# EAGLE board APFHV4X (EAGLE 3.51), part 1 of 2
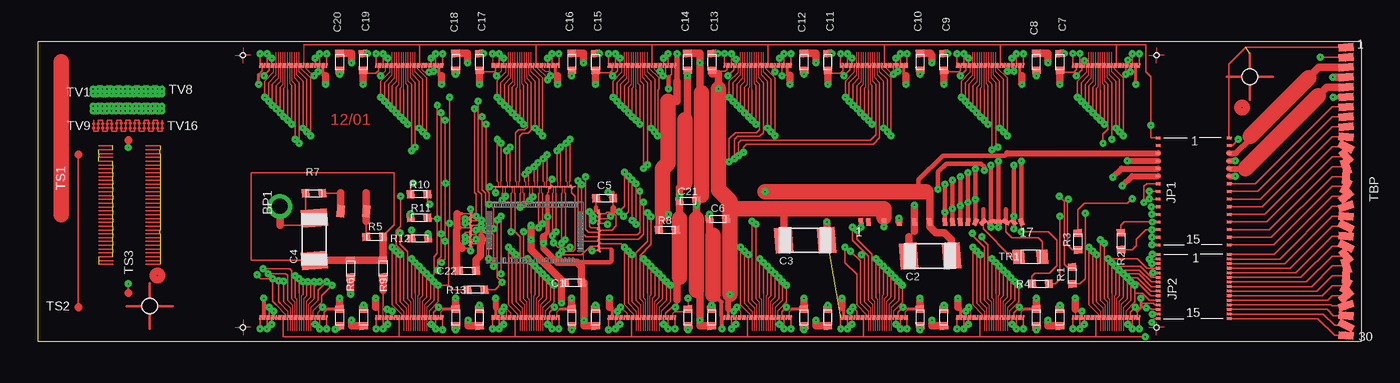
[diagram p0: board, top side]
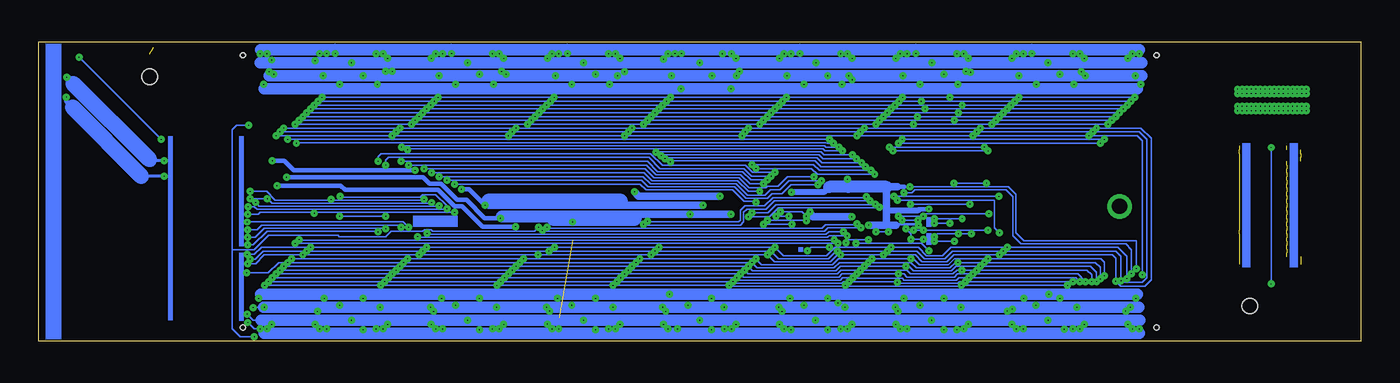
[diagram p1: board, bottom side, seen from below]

Size 86.6 x 19.6 mm. Coordinates in mm from the lower left corner, seen from the top.
Outline: 0,0 86.6,0 86.6,19.6 0,19.6 0,0
Copper layers used: Top, Bottom
Holes 0.3 mm at 73.2,18.7 73.2,0.9 13.4,0.9 13.4,18.7
Holes 1 mm at 79.3,17.3 7.3,2.3
tRestrict: area 77.3,-9.6 to 87.3,3.4

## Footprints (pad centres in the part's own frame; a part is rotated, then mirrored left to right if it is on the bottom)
200 = smd 0.5 x 0.3 rotated 5.8:  0,0
02 = smd 0.5 x 0.55 rotated 4.3:  -0.55,0 | smd 0.5 x 0.55 rotated 4.4:  0.55,0
06 = smd 1.15 x 1.7 rotated 4.3:  -1.4,0 | smd 1.15 x 1.7 rotated 4.4:  1.4,0
GTAIL = smd 0.3 x 0.5 rotated 4.3:  0,0;  7,0 | smd 0.3 x 0.5 rotated 4.4:  0.5,0 | smd 0.3 x 0.5 rotated 4.5:  1.5,0 | smd 0.3 x 0.5 rotated 4.6:  2.5,0 | smd 0.3 x 0.5 rotated 4.7:  3.5,0;  4.5,0 | smd 0.3 x 0.5 rotated 4.8:  5.5,0 | smd 0.3 x 0.5 rotated 4.9:  6,0 | smd 0.3 x 0.5 rotated 5:  6.5,0 | smd 0.3 x 0.5 rotated 26.8:  7.5,0 | smd 0.3 x 0.5 rotated 49.3:  8,0 | smd 0.3 x 0.5 rotated 71.8:  8.5,0 | smd 0.3 x 0.5 rotated 94.3:  9,0 | smd 0.3 x 0.5 rotated 116.8:  9.5,0 | smd 0.3 x 0.5 rotated 139.3:  10,0 | smd 0.3 x 0.5 rotated 161.8:  10.5,0
BP30 = smd 1 x 0.5 rotated 4.3:  0,9.425;  0,3.575 | smd 1 x 0.5 rotated 4.4:  0,8.775;  0,-2.925 | smd 1 x 0.5 rotated 4.5:  0,8.125;  0,-9.425 | smd 1 x 0.5 rotated 4.6:  0,7.475 | smd 1 x 0.5 rotated 4.7:  0,6.825;  0,6.175 | smd 1 x 0.5 rotated 4.8:  0,5.525 | smd 1 x 0.5 rotated 4.9:  0,4.875 | smd 1 x 0.5 rotated 5:  0,4.225 | smd 1 x 0.5 rotated 26.8:  0,2.925 | smd 1 x 0.5 rotated 49.3:  0,2.275 | smd 1 x 0.5 rotated 71.8:  0,1.625 | smd 1 x 0.5 rotated 94.3:  0,0.975 | smd 1 x 0.5 rotated 116.8:  0,0.325 | smd 1 x 0.5 rotated 139.3:  0,-0.325 | smd 1 x 0.5 rotated 161.8:  0,-0.975 | smd 1 x 0.5 rotated 184.3:  0,-1.625 | smd 1 x 0.5 rotated 206.8:  0,-2.275 | smd 1 x 0.5 rotated 26.9:  0,-3.575 | smd 1 x 0.5 rotated 49.4:  0,-4.225 | smd 1 x 0.5 rotated 71.9:  0,-4.875 | smd 1 x 0.5 rotated 94.4:  0,-5.525 | smd 1 x 0.5 rotated 116.9:  0,-6.175 | smd 1 x 0.5 rotated 139.4:  0,-6.825 | smd 1 x 0.5 rotated 161.9:  0,-7.475 | smd 1 x 0.5 rotated 184.4:  0,-8.125 | smd 1 x 0.5 rotated 206.9:  0,-8.775
-I = smd 0.1 x 0.3 rotated 5.8: 0 1.525,0; 0 3.025,0; 0 4.525,0; 1 1.675,0; 1 3.175,0; 1 4.675,0; 2 1.825,0; 2 3.325,0; 2 4.825,0; 3 1.975,0; 3 3.475,0; 3 4.975,0; 4 2.125,0; 4 3.625,0; 4 5.125,0; 5 2.275,0; 5 3.775,0; 5 5.275,0; 6 2.425,0; 6 3.925,0; 6 5.425,0; 7 2.575,0; 7 4.075,0; 7 5.575,0; 8 2.725,0; 8 4.225,0; 8 5.725,0; 9 2.875,0; 9 4.375,0; 9 5.875,0
-SP = smd 0.5 x 0.8 rotated 5.8:  0,0
ACK15C = smd 0.3 x 0.2 rotated 5.8: 0 4.65,0.75; 0 4.65,-0.75; 0 4.65,-2.25; 1 0,0.45; 1 0,-1.05; 2 4.65,0.45; 2 4.65,-1.05; 3 0,0.15; 3 0,-1.35; 4 4.65,0.15; 4 4.65,-1.35; 5 0,-0.15; 5 0,-1.65; 6 4.65,-0.15; 6 4.65,-1.65; 7 0,-0.45; 7 0,-1.95; 8 4.65,-0.45; 8 4.65,-1.95; 9 0,-0.75; 9 0,-2.25;  0,1.95;  4.65,1.95;  0,1.65;  4.65,1.65;  0,1.35;  4.65,1.35;  0,1.05;  4.65,1.05;  0,0.75
ACK15 = smd 0.3 x 0.2 rotated 5.8: 0 4.65,1.5; 0 4.65,-1; 0 4.65,-3.5; 1 0,1; 1 0,-1.5; 2 4.65,1; 2 4.65,-1.5; 3 0,0.5; 3 0,-2; 4 4.65,0.5; 4 4.65,-2; 5 0,0; 5 0,-2.5; 6 4.65,0; 6 4.65,-2.5; 7 0,-0.5; 7 0,-3; 8 4.65,-0.5; 8 4.65,-3; 9 0,-1; 9 0,-3.5;  0,3.5;  4.65,3.5;  0,3;  4.65,3;  0,2.5;  4.65,2.5;  0,2;  4.65,2;  0,1.5
03 = smd 0.75 x 0.95 rotated 4.4:  0.775,0 | smd 0.75 x 0.95 rotated 4.3:  -0.775,0
C_DSM = smd 0.3 x 0.1 rotated 97.6: 0 6.9,-4.175; 1 6.9,-2.825; 2 6.9,-1.775; 4 -1.5,-1.925; 5 -1.5,-2.825; 6 -1.5,-4.175 | smd 0.3 x 0.1 rotated 321.2: 0 6.9,-4.325; 1 6.9,-2.975; 2 6.9,-1.925; 4 -1.5,-1.775; 5 -1.5,-2.675; 6 -1.5,-4.025 | smd 0.1 x 0.3 rotated 96: 0N 4.95,-0.15; 0P 4.8,-0.15; 1N 4.35,-0.15; 1P 4.2,-0.15; 2N 3.45,-0.15; 2P 3.3,-0.15; 3N 2.85,-0.15; 3P 2.7,-0.15; 4N 2.25,-0.15; 4P 2.1,-0.15; 5N 1.65,-0.15; 5P 1.5,-0.15; 6N 1.05,-0.15; 6P 0.9,-0.15; 7N 0.45,-0.15; 7P 0.3,-0.15; 8N 0.15,-0.15; 8P 0,-0.15; 9N 0.75,-0.15; 9P 0.6,-0.15; 10N 1.35,-0.15; 10P 1.2,-0.15; 11N 1.95,-0.15; 11P 1.8,-0.15; 12N 2.55,-0.15; 12P 2.4,-0.15; 13N 3.15,-0.15; 13P 3,-0.15; 14N 4.05,-0.15; 14P 3.9,-0.15; 15N 4.65,-0.15; 15P 4.5,-0.15 | smd 0.3 x 0.1 rotated 96: 2N 6.9,-3.575; 2P 6.9,-3.425; N 6.9,-3.275; P 6.9,-3.125 | smd 0.1 x 0.3 rotated 97.6: 3 3.6,-0.15 | smd 0.1 x 0.3 rotated 321.2: 3 3.75,-0.15 | smd 0.1 x 0.3 rotated 74.7: B 5.25,-0.15 | smd 0.3 x 0.1 rotated 74.7: B 6.9,-3.725 | smd 0.3 x 0.1 rotated 209.8: CN -1.5,-3.575; CP -1.5,-3.725 | smd 0.3 x 0.1 rotated 298.2: DSM -1.5,-3.875 | smd 0.3 x 0.1 rotated 75.2: INN -1.5,-3.275; INP -1.5,-3.425; N -1.5,-2.975; P -1.5,-3.125 | smd 0.3 x 0.1 rotated 141.7: N -1.5,-2.075; P -1.5,-2.225 | smd 0.3 x 0.1 rotated 73.5: N 6.9,-2.525; P 6.9,-2.375 | smd 0.3 x 0.1 rotated 97.3: ON -1.5,-2.375; OP -1.5,-2.525 | smd 0.3 x 0.1 rotated 74.9: OUT 6.9,-2.675 | smd 0.1 x 0.3 rotated 28.5:  5.1,-0.15 | smd 0.3 x 0.1 rotated 253.4:  6.9,-2.225;  6.9,-2.075 | smd 0.3 x 0.1 rotated 73.4:  6.9,-3.875 | smd 0.3 x 0.1 rotated 96.7:  6.9,-4.025

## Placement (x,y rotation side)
BP1  SENSOR  [200]  15.82,8.83 270 top
C1  0.1  [02]  35.02,3.83 0 top
C2  4.7  [06]  58.38,5.58 180 top
C3  4.7  [06]  50.2,6.6 180 top
C4  .001 1kV  [06]  18.07,6.68 270 top
C5  0.1  [02]  37.07,9.35 180 top
C6  0.1  [02]  44.47,8 0 top
C7  0.1  [02]  66.88,18.27 90 top
C8  0.1  [02]  65.32,18.27 270 top
C9  0.1  [02]  59.27,18.27 90 top
C10  0.1  [02]  57.72,18.27 270 top
C11  0.1  [02]  51.67,18.27 90 top
C12  0.1  [02]  50.12,18.27 270 top
C13  0.1  [02]  44.1,18.27 90 top
C14  0.1  [02]  42.5,18.27 270 top
C15  0.1  [02]  36.47,18.27 90 top
C16  0.1  [02]  34.92,18.27 270 top
C17  0.1  [02]  28.87,18.27 90 top
C18  0.1  [02]  27.32,18.27 270 top
C19  0.1  [02]  21.27,18.27 90 top
C20  0.1  [02]  19.72,18.27 270 top
C21  0.1  [02]  42.52,9.18 0 top
C22  0.1  [02]  28.1,4.6 180 top
C23  0.1  [02]  19.72,1.55 270 top
C24  0.1  [02]  21.3,1.55 90 top
C25  0.1  [02]  27.32,1.55 270 top
C26  0.1  [02]  28.87,1.55 90 top
C27  0.1  [02]  34.92,1.55 270 top
C28  0.1  [02]  36.47,1.55 90 top
C29  0.1  [02]  42.52,1.55 270 top
C30  0.1  [02]  44.07,1.55 90 top
C31  0.1  [02]  50.12,1.55 270 top
C32  0.1  [02]  51.67,1.55 90 top
C33  0.1  [02]  57.72,1.55 270 top
C34  0.1  [02]  59.27,1.55 90 top
C35  0.1  [02]  65.32,1.55 270 top
C36  0.1  [02]  66.88,1.55 90 top
CN_PT_  PIGTAIL  [GTAIL]  53.85,7.8 0 top
CN_T  T_BP30  [BP30]  85.6,9.8 0 top
FE-0  FE-I  [-I]  73.6,18.05 180 top
FE-1  FE-I  [-I]  66,18.05 180 top
FE-2  FE-I  [-I]  58.4,18.05 180 top
FE-3  FE-I  [-I]  50.8,18.05 180 top
FE-4  FE-I  [-I]  43.2,18.05 180 top
FE-5  FE-I  [-I]  35.6,18.05 180 top
FE-6  FE-I  [-I]  28,18.05 180 top
FE-7  FE-I  [-I]  20.4,18.05 180 top
FE-8  FE-I  [-I]  13,1.55 0 top
FE-9  FE-I  [-I]  20.6,1.55 0 top
FE-10  FE-I  [-I]  28.2,1.55 0 top
FE-11  FE-I  [-I]  35.8,1.55 0 top
FE-12  FE-I  [-I]  43.4,1.55 0 top
FE-13  FE-I  [-I]  51,1.55 0 top
FE-14  FE-I  [-I]  58.6,1.55 0 top
FE-15  FE-I  [-I]  66.2,1.55 0 top
HV_PT1  VDET  [-SP]  19.8,8.5 180 top
HV_PT2  VDET_ret  [-SP]  21.47,8.5 180 top
JP2_  JPACK15C  [ACK15C]  73.3,3.73 0 top
JPA_  JPACK15  [ACK15]  73.3,9.8 0 top
R1  Zout  [02]  67.67,4.3 270 top
R2  Zin  [02]  70.88,6.55 90 top
R3  Zout  [02]  68.05,6.53 90 top
R4  Zin  [02]  65.6,3.75 0 top
R5  1Ok  [02]  22.02,6.83 180 top
R6  *2  [02]  20.45,4.75 90 top
R7  10k  [02]  18.05,9.68 0 top
R8  0 *7  [02]  41.17,7.28 0 top
R9  *2  [02]  22.57,4.75 90 top
R10  110  [02]  24.92,9.62 180 top
R11  110  [02]  24.92,8.08 0 top
R12  110  [02]  24.97,6.73 0 top
R13  110  [02]  28.65,3.38 180 top
TR1  NTC 10k  [03]  64.95,5.53 180 top
U1  MCC_DSM  [C_DSM]  29.8,10.25 0 top

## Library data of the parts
BP1 C1-C36 CN_PT_ CN_T FE-0 FE-1-FE-15 HV_PT1 HV_PT2 JP2_ JPA_ R1-R13 TR1 U1 = 1X

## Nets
AGND: C3. C6. C7. C9. C11. C13. C15. C17. C19. C23. C25. C27. C29. C31. C33. C35. CN_PT_. FE-0.0 FE-0.3 FE-0.6 FE-0.9 FE-1.0 FE-1.3 FE-1.6 FE-1.9 FE-2.0 FE-2.3 FE-2.6 FE-2.9 FE-3.0 FE-3.3 FE-3.6 FE-3.9 FE-4.0 FE-4.3 FE-4.6 FE-4.9 FE-5.0 FE-5.3 FE-5.6 FE-5.9 FE-6.0 FE-6.3 FE-6.6 FE-6.9 FE-7.0 FE-7.3 FE-7.6 FE-7.9 FE-8.0 FE-8.3 FE-8.6 FE-8.9 FE-9.0 FE-9.3 FE-9.6 FE-9.9 FE-10.0 FE-10.3 FE-10.6 FE-10.9 FE-11.0 FE-11.3 FE-11.6 FE-11.9 FE-12.0 FE-12.3 FE-12.6 FE-12.9 FE-13.0 FE-13.3 FE-13.6 FE-13.9 FE-14.0 FE-14.3 FE-14.6 FE-14.9 FE-15.0 FE-15.3 FE-15.6 FE-15.9 JP2_.9 JPA_. R8. R9.
CCK: FE-0.1 FE-1.1 FE-2.1 FE-3.1 FE-4.1 FE-5.1 FE-6.1 FE-7.1 FE-8.1 FE-9.1 FE-10.1 FE-11.1 FE-12.1 FE-13.1 FE-14.1 FE-15.1 JP2_. U1.
CKN: CN_PT_. JPA_.7 R4. U1.
CKP: CN_PT_. JPA_.9 R4. U1.
DCIN: CN_PT_. JPA_.3 R2. U1.N
DCIP: CN_PT_. JPA_.5 R2. U1.P
DETV: BP1. C4. R7.
DGND: C1. C2. C5. C8. C10. C12. C14. C16. C18. C20. C21. C22. C24. C26. C28. C30. C32. C34. C36. CN_PT_. FE-0.4 FE-0.5 FE-0.6 FE-0.7 FE-0.8 FE-0.9 FE-1.4 FE-1.5 FE-1.7 FE-1.8 FE-1.9 FE-2.4 FE-2.5 FE-2.6 FE-2.8 FE-2.9 FE-3.4 FE-3.5 FE-3.8 FE-3.9 FE-4.4 FE-4.5 FE-4.6 FE-4.7 FE-4.9 FE-5.4 FE-5.5 FE-5.7 FE-5.9 FE-6.4 FE-6.5 FE-6.6 FE-6.9 FE-7.4 FE-7.5 FE-7.9 FE-8.4 FE-8.5 FE-8.6 FE-8.7 FE-8.8 FE-9.4 FE-9.5 FE-9.7 FE-9.8 FE-10.4 FE-10.5 FE-10.6 FE-10.8 FE-11.4 FE-11.5 FE-11.8 FE-12.4 FE-12.5 FE-12.6 FE-12.7 FE-13.4 FE-13.5 FE-13.7 FE-14.4 FE-14.5 FE-14.6 FE-15.4 FE-15.5 JP2_.5 JPA_. R8. U1.0 U1.1 U1.2 U1.3 U1.4 U1.5 U1.6 U1.DSM
DI: FE-0.2 FE-1.2 FE-2.2 FE-3.2 FE-4.2 FE-5.2 FE-6.2 FE-7.2 FE-8.2 FE-9.2 FE-10.2 FE-11.2 FE-12.2 FE-13.2 FE-14.2 FE-15.2 JP2_. U1.
DTO2N: CN_PT_. JPA_.1 R1. U1.2N
DTO2P: CN_PT_. JPA_.9 R1. U1.2P
DTON: CN_PT_. JPA_.7 R3. U1.N
DTOP: CN_PT_. JPA_.5 R3. U1.P
FE-0N: FE-0.4 U1.0N
FE-0P: FE-0.5 U1.0P
FE-1N: FE-1.4 U1.1N
FE-1P: FE-1.5 U1.1P
FE-2N: FE-2.4 U1.2N
FE-2P: FE-2.5 U1.2P
FE-3N: FE-3.4 U1.3N
FE-3P: FE-3.5 U1.3P
FE-4N: FE-4.4 U1.4N
FE-4P: FE-4.5 U1.4P
FE-5N: FE-5.4 U1.5N
FE-5P: FE-5.5 U1.5P
FE-6N: FE-6.4 U1.6N
FE-6P: FE-6.5 U1.6P
FE-7N: FE-7.4 U1.7N
FE-7P: FE-7.5 U1.7P
FE-8N: FE-8.4 U1.8N
FE-8P: FE-8.5 U1.8P
FE-9N: FE-9.4 U1.9N
FE-9P: FE-9.5 U1.9P
FE-10N: FE-10.4 U1.10N
FE-10P: FE-10.5 U1.10P
FE-11N: FE-11.4 U1.11N
FE-11P: FE-11.5 U1.11P
FE-12N: FE-12.4 U1.12N
FE-12P: FE-12.5 U1.12P
FE-13N: FE-13.4 U1.13N
FE-13P: FE-13.5 U1.13P
FE-14N: FE-14.4 U1.14N
FE-14P: FE-14.5 U1.14P
FE-15N: FE-15.4 U1.15N
FE-15P: FE-15.5 U1.15P
HV_GUARD: C4. R5. R6. R9.
LD: FE-0.3 FE-1.3 FE-2.3 FE-3.3 FE-4.3 FE-5.3 FE-6.3 FE-7.3 FE-8.3 FE-9.3 FE-10.3 FE-11.3 FE-12.3 FE-13.3 FE-14.3 FE-15.3 JP2_. U1.
LV1N: FE-0.0 FE-1.0 FE-2.0 FE-3.0 FE-4.0 FE-5.0 FE-6.0 FE-7.0 FE-8.0 FE-9.0 FE-10.0 FE-11.0 FE-12.0 FE-13.0 FE-14.0 FE-15.0 JP2_.5 R11. U1.N
LV1P: FE-0.1 FE-1.1 FE-2.1 FE-3.1 FE-4.1 FE-5.1 FE-6.1 FE-7.1 FE-8.1 FE-9.1 FE-10.1 FE-11.1 FE-12.1 FE-13.1 FE-14.1 FE-15.1 JP2_.7 R11. U1.P
N$1: CN_T. JPA_.
N$2: CN_T. JPA_.0
N$4: CN_T. JP2_.
N$5: CN_T. JP2_.
N$6: CN_T. JP2_.
N$7: CN_T. JPA_.0
N$8: CN_T. JP2_.
N$9: CN_T. JP2_.0
N$10: CN_T. JPA_.2
N$11: CN_T. JP2_.2
N$12: CN_T. JP2_.4
N$13: CN_T. JP2_.6
N$14: CN_T. JPA_.6
N$15: CN_T. JPA_.4
N$16: CN_T. JPA_.6
N$17: CN_T. JPA_.8
N$18: CN_T. JPA_.8
N$19: CN_T. JPA_.0
N$20: CN_T. JPA_.4
N$22: CN_T. JPA_.
N$23: CN_T. JPA_.
N$24: CN_T. JPA_.
N$25: CN_T. JPA_.2
N$26: CN_T. JP2_.8
N$27: CN_T. JP2_.0
N$28: CN_T. JP2_.2
N$29: CN_T. JP2_.6
N$30: CN_T. JP2_.8
N$32: CN_T. JP2_.4
N$33: CN_T. JP2_.0
NTC: CN_PT_. TR1.
NTC_RET: CN_PT_. TR1.
RSIB: CN_PT_. JPA_.3 U1.B
STRN: FE-0.2 FE-1.2 FE-2.2 FE-3.2 FE-4.2 FE-5.2 FE-6.2 FE-7.2 FE-8.2 FE-9.2 FE-10.2 FE-11.2 FE-12.2 FE-13.2 FE-14.2 FE-15.2 JP2_.9 R13. U1.ON
STRP: FE-0.3 FE-1.3 FE-2.3 FE-3.3 FE-4.3 FE-5.3 FE-6.3 FE-7.3 FE-8.3 FE-9.3 FE-10.3 FE-11.3 FE-12.3 FE-13.3 FE-14.3 FE-15.3 JP2_.1 R13. U1.OP
SYNCN: FE-0.6 FE-1.6 FE-2.6 FE-3.6 FE-4.6 FE-5.6 FE-6.6 FE-7.6 FE-8.6 FE-9.6 FE-10.6 FE-11.6 FE-12.6 FE-13.6 FE-14.6 FE-15.6 JP2_. R10. U1.CN
SYNCP: FE-0.7 FE-1.7 FE-2.7 FE-3.7 FE-4.7 FE-5.7 FE-6.7 FE-7.7 FE-8.7 FE-9.7 FE-10.7 FE-11.7 FE-12.7 FE-13.7 FE-14.7 FE-15.7 JP2_. R10. U1.CP
VCAL: CN_PT_. FE-0.0 FE-1.0 FE-2.0 FE-3.0 FE-4.0 FE-5.0 FE-6.0 FE-7.0 FE-8.0 FE-9.0 FE-10.0 FE-11.0 FE-12.0 FE-13.0 FE-14.0 FE-15.0 JPA_.
VDD: C1. C2. C5. C8. C10. C12. C14. C16. C18. C20. C21. C22. C24. C26. C28. C30. C32. C34. C36. CN_PT_. FE-0.4 FE-0.5 FE-1.4 FE-1.5 FE-2.4 FE-2.5 FE-3.4 FE-3.5 FE-4.4 FE-4.5 FE-5.4 FE-5.5 FE-6.4 FE-6.5 FE-7.4 FE-7.5 FE-8.4 FE-8.5 FE-9.4 FE-9.5 FE-10.4 FE-10.5 FE-11.4 FE-11.5 FE-12.4 FE-12.5 FE-13.4 FE-13.5 FE-14.4 FE-14.5 FE-15.4 FE-15.5 JP2_.7 JPA_. U1.0 U1.1 U1.2 U1.3 U1.4 U1.5 U1.6
VDDA: C3. C6. C7. C9. C11. C13. C15. C17. C19. C23. C25. C27. C29. C31. C33. C35. CN_PT_. FE-0.1 FE-0.2 FE-0.7 FE-0.8 FE-1.1 FE-1.2 FE-1.7 FE-1.8 FE-2.1 FE-2.2 FE-2.7 FE-2.8 FE-3.1 FE-3.2 FE-3.7 FE-3.8 FE-4.1 FE-4.2 FE-4.7 FE-4.8 FE-5.1 FE-5.2 FE-5.7 FE-5.8 FE-6.1 FE-6.2 FE-6.7 FE-6.8 FE-7.1 FE-7.2 FE-7.7 FE-7.8 FE-8.1 FE-8.2 FE-8.7 FE-8.8 FE-9.1 FE-9.2 FE-9.7 FE-9.8 FE-10.1 FE-10.2 FE-10.7 FE-10.8 FE-11.1 FE-11.2 FE-11.7 FE-11.8 FE-12.1 FE-12.2 FE-12.7 FE-12.8 FE-13.1 FE-13.2 FE-13.7 FE-13.8 FE-14.1 FE-14.2 FE-14.7 FE-14.8 FE-15.1 FE-15.2 FE-15.7 FE-15.8 JP2_.3 JPA_.1 R6.
VDET: HV_PT1. R7.
VDET_RET: HV_PT2. R5.
XCKN: FE-0.8 FE-1.8 FE-2.8 FE-3.8 FE-4.8 FE-5.8 FE-6.8 FE-7.8 FE-8.8 FE-9.8 FE-10.8 FE-11.8 FE-12.8 FE-13.8 FE-14.8 FE-15.8 JP2_.1 R12. U1.INN U1.N
XCKP: FE-0.9 FE-1.9 FE-2.9 FE-3.9 FE-4.9 FE-5.9 FE-6.9 FE-7.9 FE-8.9 FE-9.9 FE-10.9 FE-11.9 FE-12.9 FE-13.9 FE-14.9 FE-15.9 JP2_.3 R12. U1.INP U1.P

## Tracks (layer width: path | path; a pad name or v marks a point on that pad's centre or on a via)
AGND  (via drill 0.05 pad 0.2)  (1 unrouted)
  Top 0: v51.95,18.83 C11. | v67.15,18.83 C7. | v29.15,18.83 C17. | v67.15,18.83 C7. | 19.72,0.78 C23. | v27.32,0.75 C25. | v34.92,0.75 C27. | v57.72,0.75 C33. | v65.32,0.75 C35. | v67.15,18.83 C7. | 41.67,18.05 41.67,18.8 v41.82,18.8 | v50.12,0.75 C31. v50.12,0.75
  Top 0.075: v29.72,18.8 FE-5.9 | 22.57,1.55 22.57,2.3
  Top 0.1: v56.88,18.8 56.88,18.05 | v72.07,18.8 72.07,18.05 | v64.47,18.8 64.47,18.05 | FE-0.9 v67.72,18.83 67.72,18.43 | C7. 66.88,18.62 | 68.17,18.15 FE-0.6 v68.17,18.83 | v44.92,18.83 FE-3.9 | v60.12,18.8 FE-1.9 | v52.52,18.8 FE-2.9 | v37.32,18.8 FE-4.9 | 34.07,18.05 v34.07,18.8 | v26.47,18.8 26.47,18.05 | v22.12,18.8 FE-6.9 | v71.62,18.8 71.62,18.05 | v64.03,18.8 64.03,18.05 | v56.42,18.8 56.42,18.05 | v60.57,18.8 FE-1.6 | v52.97,18.8 FE-2.6 | v49.27,18.8 49.27,18.05 | v48.82,18.8 48.82,18.05 | v45.38,18.8 FE-3.6 | v41.22,18.8 41.22,18.05 | v37.77,18.8 FE-4.6 | v33.62,18.8 33.62,18.05 | v30.17,18.8 FE-5.6 | v18.87,18.8 18.87,18.05 | v18.42,18.8 18.42,18.05 | v14.52,18.8 FE-7.9 | v14.97,18.8 FE-7.6 | v14.52,0.8 14.52,1.55 | v14.97,0.8 14.97,1.55 | v18.87,0.8 FE-8.9 | v18.42,0.8 FE-8.6 | v22.12,0.8 22.12,1.55 | v22.57,0.8 22.57,1.55 | v26.47,0.75 FE-9.9 | v26.02,0.8 FE-9.6 | v29.72,0.8 29.72,1.55 | v30.17,0.8 30.17,1.55 | v34.07,0.8 FE-10.9 | v33.62,0.8 FE-10.6 | v37.32,0.75 37.32,1.55 | v37.77,0.8 37.77,1.55 | v45.38,0.8 45.38,1.55 | v41.67,0.8 FE-11.9 | v41.22,0.8 FE-11.6 | 44.75,1.55 44.92,1.55 | v49.27,0.8 FE-12.9 | v48.82,0.8 FE-12.6 | 52.52,1.55 v52.52,0.8 | v52.97,0.8 52.97,1.55 | v56.88,0.8 FE-13.9 | v56.42,0.8 FE-13.6 | v60.12,0.8 60.12,1.55 | v60.57,0.8 60.57,1.55 | v64.03,0.8 FE-14.6 | v64.47,0.8 FE-14.9 | v67.72,0.8 67.72,1.55 | v68.17,0.8 68.17,1.55 | v71.62,0.8 FE-15.6 | v72.07,0.8 FE-15.9 | JP2_.9 73.05,1.48 72.88,1.3 v72.88,1.23 | v26.02,18.8 26.02,18.05 | v22.57,18.8 FE-6.6 | 22.57,2.3 22.57,3.33 | 40.85,8.3 v41.25,8.3
  Top 0.2: v67.15,18.83 C7. | v59.55,18.83 C9. | v51.95,18.83 C11. | v36.75,18.83 C15. | v29.15,18.83 C17. | v21.55,18.83 C19. | v19.45,0.78 19.72,0.78 | v27.32,0.75 C25. | v34.92,0.75 C27. | v50.12,0.75 C31. | v57.72,0.75 C33. | v65.32,0.75 C35. | v44.5,18.83 C13. | v42.52,0.75 C29.
  Top 0.25: v44.75,0.8 44.75,1.55 44.75,1.6 44.72,1.62 44.72,2.55 44.22,3.05 44.17,3.05
  Top 0.35: 41.82,15.7 41.8,15.68 | v41.82,18.8 41.82,17
  Top 0.4: JPA_. 70.92,11.3 v70.35,10.73
  Top 0.5: 41.82,17 41.82,15.7 41.22,15.7 | v56.35,8.05 56.35,7.8 | 51.6,6.6 51.62,6.6 v51.62,7.8 | 44.17,7.03 43.92,7.03 43.92,8 v43.92,8.3 | 40.85,8.3 40.62,8.08 40.62,7.28 | 22.57,3.33 22.57,4.2
  Top 1: 40.85,8.3 40.85,11.28 41.22,11.65 41.22,15.7 | 44.17,3.05 44.17,6.93
  Bottom 0: 36.5,0.53 34.07,0.53 v34.07,0.8 33.77,0.78 | 36.5,0.53 36.5,0.65 | 36.5,0.53 37.32,0.53 v37.32,0.75 37.62,0.75 | 22.27,19.08 v22.12,18.8 v22.57,18.8 | 18.72,18.8 18.72,19.08 | 21.55,19.45 21.55,19.08 v21.55,18.83 21.2,19.18 20.85,19.18 20.47,18.8 v18.87,18.8 | 60.5,18.8 60.27,19.08 | 56.72,18.8 56.72,19.08 | 60.5,18.8 60.25,18.83 v59.55,18.83 | v59.55,18.83 59.52,18.8 | 64.32,18.8 64.32,19.08 | 64.32,18.8 64.42,18.8 64.45,18.83 C7. | v60.57,18.8 v64.03,18.8 | v60.57,18.8 60.5,18.8 | v64.03,18.8 64.32,18.8 | v59.55,18.83 59.55,19.45 | v59.55,18.83 59.55,19.08 | v59.55,18.83 v60.12,18.8 60.5,18.8 | v72.07,18.8 71.92,19.08 72.05,19.08 | v29.72,18.8 29.87,19.08 | 26.32,18.8 26.32,19.08 | v29.72,18.8 29.85,18.83 v29.15,18.83 | v29.15,18.83 29.12,18.8 v26.47,18.8 | v26.47,18.8 26.32,18.8 | v29.15,18.83 29.15,19.45 | v29.15,18.83 29.15,19.08 | v29.72,18.8 29.17,18.8 v29.15,18.83 | v29.15,18.83 26.35,18.83 26.32,18.8 | 26.32,18.8 26.1,18.8 | 26.1,18.8 v26.02,18.8 | v26.02,18.8 v22.57,18.8 | v67.15,18.83 67.15,19.45 | v67.15,18.83 67.15,19.08 | 56.85,18.83 v56.88,18.8 56.72,18.8 | v59.55,18.83 56.75,18.83 56.72,18.8 | 67.88,19.08 67.88,18.8 v67.72,18.83 | v67.72,18.83 v67.15,18.83 | v72.07,18.8 68.03,18.8 | v67.72,18.83 67.17,18.8 | v52.52,18.8 52.67,19.08 | v52.52,18.8 52.65,18.83 v51.95,18.83 | v51.95,18.83 51.92,18.8 | v52.97,18.8 v56.42,18.8 | v52.97,18.8 v52.52,18.8 | v56.42,18.8 56.72,18.8 | v51.95,18.83 51.95,19.45 | v51.95,18.83 51.95,19.08 | v52.52,18.8 51.97,18.8 v51.95,18.83 | v51.95,18.83 v49.27,18.8 49.27,19.08 | 41.52,18.8 41.52,19.08 | 41.3,18.8 41.65,18.83 | 41.52,18.8 41.55,18.83 | v37.32,18.8 37.47,19.08 36.75,19.08 v36.75,18.83
  Bottom 0: 33.92,19.08 33.92,18.8 | v37.32,18.8 37.45,18.83 v36.75,18.83 | v36.75,18.83 36.72,18.8 | 41.3,18.8 41.52,18.8 | v37.77,18.8 v41.22,18.8 | v41.22,18.8 41.3,18.8 | v37.32,18.8 v37.77,18.8 | v36.75,18.83 36.75,19.45 | v37.32,18.8 36.77,18.8 v36.75,18.83 | 33.7,18.8 33.92,18.8 | v33.62,18.8 33.7,18.8 | v33.62,18.8 v30.17,18.8 | v30.17,18.8 30.1,18.8 | 30.1,18.8 v29.72,18.8 | 34.05,18.83 34.02,18.8 33.92,18.8 | v36.75,18.83 33.95,18.83 33.92,18.8 | 14.67,19.08 14.67,18.8 v14.97,18.8 | 18.72,18.8 v18.42,18.8 | v18.42,18.8 v14.97,18.8 | v18.87,0.8 18.72,0.53 | v22.12,0.8 20.52,0.8 20.15,0.43 19.8,0.43 v19.45,0.78 19.35,0.78 19.32,0.8 v18.87,0.8 | v18.87,18.8 18.72,18.8 | 29.85,0.78 29.87,0.8 v30.17,0.8 | 29.77,0.75 29.82,0.75 | 29.77,0.75 v27.32,0.75 v26.47,0.75 26.32,0.8 | v33.62,0.8 v30.17,0.8 | v33.62,0.8 33.92,0.8 33.97,0.75 v34.92,0.75 34.97,0.8 37.47,0.8 | 37.47,0.8 37.45,0.78 | 37.47,0.8 37.55,0.8 | 41.67,0.53 v41.67,0.8 | 44.1,0.53 43.65,0.53 | v41.67,0.8 41.38,0.78 | 44.92,0.53 44.92,0.75 45.22,0.75 | 44.1,0.53 44.1,0.65 | 44.1,0.53 44.42,0.53 44.42,0.68 44.45,0.7 | v41.22,0.8 v37.77,0.8 | v41.67,0.8 v41.22,0.8 | v37.77,0.8 37.47,0.8 | 44.92,0.8 45.05,0.78 | 44.92,0.8 45.15,0.8 | 49.12,0.8 49.27,0.53 v49.27,0.8 | 51.7,0.53 50.12,0.53 v50.12,0.75 52.75,0.8 52.67,0.8 | 49.12,0.8 48.97,0.78 | 51.7,0.53 51.7,0.65 | 51.7,0.53 52.52,0.53 v52.52,0.8 52.82,0.75 | v48.82,0.8 v45.38,0.8 | 49.12,0.8 v48.82,0.8 | v45.38,0.8 44.92,0.8 | 52.67,0.8 52.65,0.78 | 56.88,0.53 56.72,0.8 | 56.88,0.53 59.3,0.53 | 56.72,0.8 56.57,0.78 | 60.12,0.53 60.12,0.75 60.42,0.75 | 59.3,0.53 59.3,0.65 | 59.3,0.53 60.12,0.53 | v52.97,0.8 v56.42,0.8 | v56.42,0.8 56.72,0.8 | v52.97,0.8 52.67,0.8
  Bottom 0: 60.27,0.8 60.25,0.78 | 60.27,0.8 60.35,0.8 | 56.72,0.8 v57.72,0.75 | 64.47,0.53 64.32,0.8 | 64.47,0.53 66.9,0.53 | 64.32,0.8 64.17,0.78 | 67.72,0.53 67.72,0.75 68.03,0.75 | 66.9,0.53 66.9,0.65 | 67.72,0.53 66.9,0.53 | v60.57,0.8 v64.03,0.8 | v64.03,0.8 64.32,0.8 | v60.57,0.8 60.27,0.8 | 67.88,0.8 67.85,0.78 | 67.88,0.8 67.95,0.8 v65.32,0.75 64.32,0.8 | v68.17,0.8 67.88,0.8 | v68.17,0.8 v71.62,0.8 | v71.62,0.8 71.92,0.8 | 14.67,0.53 v14.52,0.8 v14.97,0.8 | v14.97,0.8 v18.42,0.8 v18.87,0.8 | 42.52,0.53 v41.67,0.8 | 42.52,0.53 43.3,0.58 | 45.02,19.08 45.07,19.02 | 56.5,19.08 v56.42,18.8 | v72.07,18.8 v71.62,18.8 | 41.67,19.08 v41.82,18.8 41.67,19.05 41.7,19.08 | 44.5,19.08 v44.5,18.83 v44.92,18.83 45.3,18.83 45.3,19.08 | 48.9,19.08 48.9,18.8 | 41.3,19.08 41.3,18.8 | v67.72,18.83 v68.17,18.83 68.1,19.08 | 33.7,18.8 33.7,19.08 | 37.7,19.08 v37.77,18.8 | 30.1,18.8 30.1,19.08 | 26.47,19.08 v26.47,18.8 | 26.1,18.8 26.02,19.08 v26.02,18.8 | 22.5,19.08 v22.57,18.8 | 64.03,19.08 v64.03,18.8 | 64.47,19.08 v64.47,18.8 | 60.57,19.08 v60.57,18.8 | 52.97,19.08 v52.97,18.8 | 48.82,19.08 v48.82,18.8 | 45.38,19.08 v45.38,18.8 | 41.22,19.08 v41.22,18.8 | v33.62,18.8 v34.07,18.8 34.07,19.08 | v30.17,18.8 30.17,19.08 | 18.87,19.08 v18.87,18.8 | 18.42,19.08 v18.42,18.8 | 14.52,19.08 v14.52,18.8 | 14.97,19.08 v14.97,18.8 | 14.97,0.53 v14.97,0.8 | 18.87,0.53 v18.87,0.8 | 22.57,0.53 v22.57,0.8 | 26.02,0.53 v26.02,0.8 | 29.77,0.75 29.77,0.58 29.72,0.53 v29.72,0.8 | 30.17,0.53 v30.17,0.8 | 33.62,0.53 v33.62,0.8 | 37.77,0.53 v37.77,0.8 | 45.38,0.53 v45.38,0.8 | 41.22,0.53 v41.22,0.8 | 42.52,0.53 v42.52,0.75 | 44.92,0.8 v44.75,0.8 44.75,0.53 | 48.82,0.53 v48.82,0.8 | 52.97,0.53 v52.97,0.8
  Bottom 0: 56.88,0.53 v56.88,0.8 | v56.42,0.8 56.42,0.55 56.45,0.53 | 60.12,0.53 v60.12,0.8 | 60.57,0.53 v60.57,0.8 | 64.03,0.53 v64.03,0.8 | 64.47,0.53 v64.47,0.8 | 67.72,0.53 v67.72,0.8 | 68.17,0.53 v68.17,0.8 | v71.62,0.8 71.62,0.53 72.07,0.53 v72.07,0.8 | 51.62,8.05 v51.62,7.8
  Bottom 0.1: 71.92,0.8 v72.07,0.8 72.45,0.8 v72.88,1.23
  Bottom 0.3: v56.35,8.05 57.38,8.05 58.57,9.25 59.17,9.25 60.22,10.3 60.97,10.3 61.4,10.73 v70.35,10.73
  Bottom 0.5: 56.25,8.15 v56.35,8.05 | v41.25,8.3 v43.92,8.3 47.6,8.3 47.6,8.05
  Bottom 0.75: 64.47,0.53 66.62,0.53 | 33.62,0.53 34.07,0.53 37.32,0.53 37.77,0.53 | 22.57,0.53 18.87,0.53 14.97,0.53 14.52,0.53 | 14.52,19.08 14.97,19.08 18.42,19.08 18.87,19.08 21.55,19.08 22.27,19.08 22.5,19.08 26.02,19.08 26.47,19.08 30.1,19.08 30.17,19.08 33.7,19.08 33.92,19.08 34.07,19.08 37.47,19.08 37.7,19.08 41.22,19.08 41.3,19.08 41.67,19.08 41.7,19.08 44.5,19.08 45.02,19.08 45.3,19.08 45.38,19.08 48.82,19.08 48.9,19.08 49.27,19.08 52.97,19.08 56.5,19.08 60.57,19.08 64.03,19.08 64.47,19.08 68.1,19.08 72.05,19.08 | 42.52,0.53 41.67,0.53 41.22,0.53 | 71.8,0.53 71.62,0.53 68.17,0.53 67.72,0.53 64.47,0.53 | 22.57,0.53 26.02,0.53 29.72,0.53 30.17,0.53 33.62,0.53 | 22.57,0.53 22.12,0.53 | 52.52,0.53 50.12,0.53 | 37.77,0.53 33.62,0.53 | 42.52,0.53 43.65,0.53 44.42,0.53 44.75,0.53 44.92,0.53 45.38,0.53 48.82,0.53 49.27,0.53 50.12,0.53 | 42.52,0.53 41.22,0.53 | 41.22,0.53 37.77,0.53 | 50.12,0.53 52.97,0.53 56.45,0.53 56.88,0.53 60.12,0.53 60.57,0.53 64.03,0.53 64.47,0.53
  Bottom 0.8: 52.85,8.05 52.95,8.15 56.25,8.15
  Bottom 1: 47.6,8.05 51.62,8.05 52.85,8.05
CCK  (via drill 0.05 pad 0.2)
  Top 0.075: 17.82,17.23 17.22,17.83 17.22,18.05 | 25.42,17.23 24.82,17.83 24.82,18.05 | 33.02,17.23 32.42,17.83 32.42,18.05 | 40.62,17.23 40.02,17.83 40.02,18.05 | 48.22,17.23 47.62,17.83 47.62,18.05 | 55.82,17.23 55.22,17.83 55.22,18.05 | 63.42,17.23 62.82,17.83 62.82,18.05 | 71.03,17.23 70.42,17.83 70.42,18.05 | 15.57,2.38 16.17,1.78 16.17,1.55 | 23.17,2.38 23.77,1.78 23.77,1.55 | 30.77,2.38 31.37,1.78 31.37,1.55 | 38.38,2.38 38.97,1.78 38.97,1.55 | 53.57,2.38 54.17,1.78 54.17,1.55 | 61.17,2.38 61.77,1.78 61.77,1.55 | 68.78,2.38 69.38,1.78 69.38,1.55 | 45.97,2.38 46.57,1.78 46.57,1.55
  Top 0.1: v14.32,4.35 14.57,4.1 v15.35,4.1 15.35,2.6 15.57,2.38 | v72.92,5.68 73.3,5.68 | v17.82,13.45 17.82,17.23 | v25.42,13.45 25.42,17.23 | v33.02,13.45 33.02,17.23 | v40.52,13.45 40.57,13.45 40.57,16.45 40.62,16.5 40.62,17.23 | v48.22,13.45 48.22,17.23 | v55.82,13.45 55.82,17.23 | v63.42,13.45 63.42,17.23 | v71.03,13.45 71.03,17.23 | v23.17,6.15 23.17,2.38 | v30.77,6.15 30.77,2.38 | 38.38,2.38 v38.38,6.15 38.15,6.38 36.7,6.38 | 53.57,2.38 53.57,4.38 52.8,5.15 v52.8,6.15 | v61.17,6.15 61.17,2.38 | v68.78,6.15 68.78,2.38 | v45.97,6.15 45.97,2.38
  Bottom 0.1: v71.03,13.45 v63.42,13.45 v55.82,13.45 v48.22,13.45 v40.52,13.45 v33.02,13.45 v25.42,13.45 v17.82,13.45 14.65,13.45 14.32,13.12 v14.32,4.35 | v72.92,5.68 72.45,5.68 71.97,6.15 v68.78,6.15 v61.17,6.15 v52.8,6.15 v45.97,6.15 v38.38,6.15 37.82,5.6 35,5.6 34.45,6.15 v30.77,6.15 29,6.15 28.45,5.6 27.42,5.6 26.87,6.15 v23.17,6.15 15.92,6.15 15.35,5.58 v15.35,4.1
CKN  (via drill 0.05 pad 0.2)
  Top 0.1: v72.9,6.8 JPA_.7 | 63.85,7.8 v63.85,7.35 | v37.47,8.18 37.32,8.03 36.7,8.03 | v38.62,10.8 38.62,8.48 38.32,8.18 v38.3,8.18 | R4. 66.57,3.75 66.88,4.05 v66.88,8.18
  Top 0.3: v63.85,11.53 v63.85,8.18 63.85,7.8
  Bottom 0.1: v72.9,6.8 72.4,6.8 71.8,7.4 63.9,7.4 v63.85,7.35 | v38.62,10.8 39.9,10.8 40.4,11.3 45.9,11.3 46.62,12.03 63.67,12.03 63.85,11.85 v63.85,11.53 | v63.85,8.18 v66.88,8.18 | v38.3,8.18 v37.47,8.18
CKP  (via drill 0.05 pad 0.2)
  Top 0.1: v72.9,6.3 JPA_.9 | CN_PT_. v64.35,7.15 66.12,7.15 66.67,6.6 66.67,4.95 66.17,4.45 65.25,4.45 65.05,4.25 65.05,3.75 | v38.38,11.05 38.38,8.83 v38.02,8.48 | v36.32,8.18 U1.
  Top 0.3: v64.35,11.78 CN_PT_.
  Bottom 0.1: v72.9,6.3 72.53,6.3 71.62,7.2 64.4,7.2 v64.35,7.15 | v38.38,11.05 39.85,11.05 40.3,11.5 45.75,11.5 46.52,12.28 64.15,12.28 64.35,12.08 v64.35,11.78 | v36.32,8.18 36.62,8.48 v38.02,8.48
DCIN  (via drill 0.05 pad 0.2)
  Top 0.1: v72.92,7.8 JPA_.3 | 62.35,7.8 v62.35,7.45 | v72.92,7.8 72.9,7.83 | v39.12,7.65 v39.12,10.3 | 36.7,7.73 37.2,7.73 v37.27,7.65 | R2. 70.88,7.58 71.1,7.8 v72.92,7.8
  Top 0.3: v62.35,11.53 62.35,7.8
  Bottom 0.1: v62.35,7.45 62.7,7.8 v72.92,7.8 | v39.12,7.65 v37.27,7.65 | v39.12,10.3 40.02,10.3 40.62,10.9 46.17,10.9 46.8,11.53 v62.35,11.53
DCIP  (via drill 0.05 pad 0.2)  (1 unrouted)
  Top 0.1: v72.9,7.3 JPA_.5 | 62.85,7.8 v62.85,7.45 | v36.32,7.88 36.7,7.88 | v38.88,7.9 v38.88,10.55 | 70.88,6 71.62,6 71.88,6.25 71.88,6.68 72.5,7.3 72.88,7.3
  Top 0.3: v62.85,11.78 62.85,7.8
  Bottom 0.1: v72.9,7.3 72.28,7.3 71.97,7.6 63,7.6 v62.85,7.45 | v38.88,10.55 39.95,10.55 40.5,11.1 46.05,11.1 46.72,11.78 v62.85,11.78 | v36.32,7.88 36.32,7.9 v38.88,7.9
DETV  (via drill 1 pad 1.6)
  Top 0.1: 15.82,7.58 17.5,7.58 17.5,9.68 17.5,8.08 18.07,8.08
  Top 0.5: 15.82,7.58 BP1.
  other vias: 15.82,8.83
DGND  (via drill 0.05 pad 0.2)
  Top 0: 40.7,18.05 40.72,18.05 | 40.72,18.05 40.77,18.05 | 40.72,18.05 40.62,18.05 | 45.97,1.55 45.82,1.55 | 34.25,2.73 v34.25,2.5 34.2,3.8 34.45,3.8 34.47,3.83 | 37.62,8.58 37.62,8.43
  Top 0.005: 33.2,17.62 33.17,17.65
  Top 0.075: 61.02,1.53 61.02,1.55 61.02,2.13 v60.92,2.23 | 40.32,18.05 40.32,17.8 40.5,17.62 40.7,17.62 | v55.97,17.48 55.92,17.48 55.52,17.88 55.52,18.05 | v56.27,17.65 56.27,18.05 | 48.07,18.05 48.07,17.77 v48.22,17.62 | 32.72,18.05 32.72,17.83 33.32,17.23 v33.32,17.1 | 33.02,18.05 33.02,17.8 33.17,17.65 | FE-5.5 30.32,17.7 v30,17.38 | 25.12,18.05 25.12,17.77 25.3,17.6 v25.57,17.6 25.57,18.05 | FE-6.5 22.72,17.7 v22.4,17.38 | 33.47,17.62 33.2,17.62 | 33.47,17.62 33.55,17.62 v33.55,17.38 | 33.47,17.62 33.47,18.05 | 17.52,18.05 17.52,17.83 17.82,17.52 17.92,17.52 v18.07,17.38 | 18.27,18.05 18.27,17.68 v18.32,17.62 | FE-8.5 18.27,1.88 v18.62,2.23 | v23.17,1.98 23.17,1.55 | v30.5,2.23 30.55,2.23 30.62,2.15 | 30.62,2.15 30.62,1.55 | 30.92,1.55 30.92,1.85 30.62,2.15 | 38.52,1.55 38.52,1.83 v38.12,2.23 | v37.92,1.95 37.92,1.55 | 45.97,1.55 45.97,1.98 v45.72,2.23 | 53.12,1.55 v53.12,1.98 | v60.72,1.95 60.72,1.55 | U1.DSM U1.6 | 22.72,1.55 22.72,1.98 v22.85,2.1
  Top 0.1: 63.27,18.05 63.12,18.05 | 63.42,18.05 63.27,18.05 | 63.42,18.05 63.27,18.05 | v71.47,17.62 71.47,18.05 | v71.17,17.48 71.17,18.05 | 70.88,18.05 70.72,18.05 | 71.03,18.05 70.88,18.05 | 71.17,18.05 71.03,18.05 | 71.03,18.05 70.88,18.05 | 71.17,18.05 71.03,18.05 | v63.88,17.65 63.88,18.05 | v63.42,17.65 63.42,18.05 | FE-1.5 60.72,17.73 v60.38,17.38 | v55.97,17.48 55.97,18.05 | 55.52,18.05 55.67,18.05 | v48.67,17.38 48.67,18.05 | 48.07,18.05 47.92,18.05 | FE-4.5 37.92,17.7 v37.6,17.38 | v25.87,17.65 25.87,18.05 | FE-2.5 53.12,17.75 v52.75,17.38 | FE-0.5 68.32,17.75 v67.95,17.38 | FE-3.5 45.52,17.75 v45.15,17.38 | 41.07,18.05 41.07,17.55 v40.9,17.38 | FE-7.5 15.12,17.73 v14.77,17.38 | 15.72,1.55 15.57,1.55 15.42,1.55 v15.42,1.98 | v15.12,2.23 15.12,1.55 | 23.17,1.55 23.32,1.55 | FE-9.5 25.87,1.9 v26.2,2.23 | v30.32,1.98 30.32,1.55 | FE-10.5 33.47,1.9 v33.8,2.23 | v41.7,2.23 41.47,2.23 41.07,1.83 FE-11.5 | v45.52,1.95 45.52,1.55 | FE-12.5 48.67,1.93 v48.97,2.23 | 53.57,1.55 53.57,1.98 v53.32,2.23 | FE-13.5 56.27,1.9 v56.6,2.23 | FE-14.5 63.88,1.88 v64.22,2.23 | v68.32,1.95 68.32,1.55 | FE-15.5 71.47,1.9 v71.8,2.23 | JP2_.5 72.85,2.08 72.72,2.2 v72.53,2.2 | 41.82,2.6 41.82,2.73 | U1.2 37.12,8.33 37.22,8.43 37.62,8.43 37.82,8.23 37.82,7.55 37.55,7.28 U1.1 | U1.3 33.55,10.53 v33.62,10.6 | v36.25,5.93 U1.0 | U1.DSM 28.95,6.38 28.95,6.2 | 37.62,9.35 37.62,8.73 | 34.47,3.83 34.47,3.9 34.35,3.9 34.25,4 | v33.72,6.45 34.02,6.15 v34.82,6.15 | 28.3,8.58 U1.4 v28.3,8.65 | v28.97,7.58 U1.5 v28.97,7.58
  Top 0.15: 40.7,17.62 v40.7,17.65 40.7,17.7
  Top 0.2: 41.82,2.7 41.82,2.6 41.82,2.35 v41.7,2.23 | 40.7,17.7 40.7,18.05 | v21.3,2.35 C24. | v28.87,2.35 C26. | v36.47,2.35 C28. | v44.07,2.35 C30. | v51.67,2.35 C32. | v59.27,2.35 C34. | v66.88,2.35 C36. | v37.3,9.75 37.62,9.75 37.62,9.35
  Top 0.25: v28.97,7.58 28.97,6.93
  Top 0.3: 57.62,9.78 57.62,10.55 59.22,12.15 63.27,12.15 63.42,12.3 | v32.25,6.65 32.25,6.7
  Top 0.35: 28.97,6.93 29.05,6.85
  Top 0.4: 63.42,12.3 73.3,12.3 | 37.62,8.73 37.62,8.58 | 28.95,6.38 29.05,6.38 29.05,6.85
  Top 0.5: v65.32,17.38 C8. | v42.5,17.38 C14. 42.5,14.65 42.32,14.48 | v57.72,17.48 C10. | v50.12,17.48 C12. | v34.92,17.38 C16. | v27.32,17.48 C18. | v19.72,17.48 C20. | 42.32,10.38 41.97,10.03 v41.97,9.5 | 41.97,9.18 v41.97,9.5 | 41.97,9.18 41.97,8.03 41.72,7.78 R8. | 41.97,4.2 41.82,4.05 41.82,2.73 | 58.1,9.78 58.35,9.78 58.35,7.83 | 58.35,7.83 58.35,7.8 | 58.35,7.83 58.35,7.53 58.35,7.5 58.75,7.1 59.3,7.1 59.77,6.63 59.77,5.58 | 41.97,9.18 v41.97,9.5 | 34.25,2.73 34.25,3.83 34.47,3.83 | 32.25,6.7 v32.25,7.6 | v32.25,6.65 32.25,6 34.25,4 | 28.95,6.2 28.95,5.63 28.65,5.33 28.65,4.6
  Top 1: 42.32,10.38 42.32,14.48 | 41.97,4.2 41.97,8.03 | v47.57,9.78 57.62,9.78 58.1,9.78
  Bottom 0: 71.47,17.38 v71.47,17.62 | v63.88,17.65 63.88,17.38 63.42,17.38 v63.42,17.65 | 44.8,17.38 45.52,17.55 | 40.7,17.38 v40.7,17.65 40.7,17.7 | 55.97,17.38 v55.97,17.48 | 56.27,17.38 v56.27,17.65 | 57.72,17.38 v57.72,17.48 | 50.12,17.38 v50.12,17.48 | 48.22,17.38 v48.22,17.62 | 33.47,17.38 33.47,17.65 | 27.32,17.38 v27.32,17.48 | 25.87,17.38 v25.87,17.65 | 25.57,17.38 v25.57,17.6 | 19.72,17.38 v19.72,17.48 | 71.17,17.38 v71.17,17.48 | 33.32,17.38 33.32,17.23 | v33.55,17.38 33.32,17.38 | 33.32,17.38 v33.32,17.1 | v18.07,17.38 v18.32,17.62 | 15.42,2.23 v15.42,1.98 | 23.17,2.23 v23.17,1.98 | 21.3,2.23 v21.3,2.35 | 22.72,2.23 v22.85,2.1 | 28.87,2.23 v28.87,2.35 | 30.32,2.23 v30.32,1.98 | v30.5,2.23 30.62,1.98 | 36.47,2.23 v36.47,2.35 | 44.07,2.23 v44.07,2.35 | 45.52,2.23 v45.52,1.95 | v51.67,2.35 51.65,2.35 51.65,2.23 | v53.12,1.98 53.12,2.23 | 60.72,2.23 v60.72,1.95 | 59.27,2.23 v59.27,2.35 | 66.88,2.23 v66.88,2.35 | 68.32,2.23 v68.32,1.95 | 37.92,2.23 v37.92,1.95 | v34.25,2.5 33.97,2.23 v33.8,2.23
  Bottom 0.1: v71.8,2.23 72.5,2.23 v72.53,2.2 | v33.62,10.6 33.6,10.6 | 28.97,7.65 v28.97,7.58 | 30.45,7.6 30.45,7.65 | 32.2,6.65 v32.25,6.65 33.52,6.65 v33.72,6.45 | v36.25,5.93 36.02,6.15 v34.82,6.15
  Bottom 0.15: 30.45,7.65 28.97,7.65
  Bottom 0.3: 33.62,10.1 v33.62,10.6 | 30.37,10.1 29.9,10.1 | 28.97,8.58 28.9,8.65 v28.3,8.65
  Bottom 0.4: v37.3,9.75 35.17,9.75 34.82,10.1 | 31.07,8.58 28.97,8.58
  Bottom 0.5: v47.57,9.78 47.3,9.5 v41.97,9.5 | 33.6,10.1 33.62,10.1 | 30.37,10.1 31.07,10.1 31.07,8.58 31.07,7.6 | 34.82,10.1 34.85,10.1 | 31.07,7.6 30.45,7.6 | v32.25,7.6 31.07,7.6
  Bottom 0.75: 14.37,17.38 v14.77,17.38 v18.07,17.38 19.72,17.38 v22.4,17.38 25.57,17.38 25.87,17.38 27.32,17.38 v30,17.38 33.32,17.38 33.47,17.38 v33.55,17.38 v34.92,17.38 v37.6,17.38 40.7,17.38 v40.9,17.38 v42.5,17.38 44.8,17.38 v45.15,17.38 48.22,17.38 v48.67,17.38 50.12,17.38 v52.75,17.38 55.97,17.38 56.27,17.38 57.72,17.38 v60.38,17.38 63.88,17.38 v65.32,17.38 v67.95,17.38 71.17,17.38 71.47,17.38 | 71.85,2.23 v71.8,2.23 68.32,2.23 66.88,2.23 v64.22,2.23 v60.92,2.23 60.72,2.23 59.27,2.23 v56.6,2.23 v53.32,2.23 53.12,2.23 51.65,2.23 v48.97,2.23 v45.72,2.23 45.52,2.23 44.07,2.23 v41.7,2.23 v38.12,2.23 37.92,2.23 36.47,2.23 v33.8,2.23 v30.5,2.23 30.32,2.23 28.87,2.23 v26.2,2.23 23.17,2.23 22.72,2.23 21.3,2.23 v18.62,2.23 15.42,2.23 v15.12,2.23 14.57,2.23
  Bottom 0.8: 31.07,10.1 33.6,10.1 34.82,10.1
DI  (via drill 0.05 pad 0.2)
  Top 0.075: 17.57,17.12 17.07,17.62 17.07,18.05 | 25.17,17.12 24.67,17.62 24.67,18.05 | 32.77,17.12 32.27,17.62 32.27,18.05 | 40.38,17.12 39.88,17.62 39.88,18.05 | 47.97,17.12 47.47,17.62 47.47,18.05 | 55.57,17.12 55.07,17.62 55.07,18.05 | 63.17,17.12 62.67,17.62 62.67,18.05 | 70.78,17.12 70.28,17.62 70.28,18.05 | 15.82,2.48 16.32,1.98 16.32,1.55 | 23.42,2.48 23.92,1.98 23.92,1.55 | 31.02,2.48 31.52,1.98 31.52,1.55 | 38.62,2.48 39.12,1.98 39.12,1.55 | 53.82,2.48 54.32,1.98 54.32,1.55 | 61.42,2.48 61.92,1.98 61.92,1.55 | 69.03,2.48 69.53,1.98 69.53,1.55 | 46.22,2.48 46.72,1.98 46.72,1.55
  Top 0.1: v72.72,5.38 73.3,5.38 | v17.57,13.7 17.57,17.12 | v25.17,13.7 25.17,17.12 | v32.77,13.7 32.77,17.12 | v40.32,13.7 40.38,13.7 40.38,17.12 | v47.97,13.7 47.97,17.12 | v55.57,13.7 55.57,17.12 | v63.17,13.7 63.17,17.12 | v70.78,13.7 70.78,17.12 | 15.72,3.98 v15.72,3.95 15.72,2.58 15.82,2.48 | v23.42,5.9 23.42,2.48 | v31.02,5.9 31.02,2.48 | v38.62,5.9 38.62,2.48 | 53.82,2.48 53.82,5.25 v53.17,5.9 | v61.42,5.9 61.42,2.48 | v69.03,5.9 69.03,2.48 | v46.22,5.9 46.22,2.48 | 34.9,10.1 34.9,9.7 35.12,9.48 35.12,6.03 35,5.9 v34.27,5.9
  Bottom 0.1: v70.78,13.7 v63.17,13.7 v55.57,13.7 v47.97,13.7 v40.32,13.7 v32.77,13.7 v25.17,13.7 v17.57,13.7 14.52,13.7 14.02,13.2 14.02,4.15 14.32,3.85 15.62,3.85 v15.72,3.95 15.72,5.58 16.05,5.9 v23.42,5.9 26.75,5.9 27.25,5.4 28.6,5.4 29.1,5.9 v31.02,5.9 v34.27,5.9 34.38,5.9 34.88,5.4 38.15,5.4 38.62,5.88 v38.62,5.9 v46.22,5.9 v53.17,5.9 v61.42,5.9 v69.03,5.9 71.88,5.9 72.4,5.38 v72.72,5.38
DTO2N  (via drill 0.05 pad 0.2)
  Top 0.1: v72.88,8.3 JPA_.1 | v39.62,9.1 39.62,7 39.3,6.68 U1.2N | R1. 68.17,3.75 68.53,4.1 v68.53,8.38
  Top 0.3: 59.35,7.8 v59.35,8.43 v59.35,10.28
  Bottom 0.1: v59.35,8.43 68.53,8.43 | 68.53,8.43 72.07,8.43 72.2,8.3 v72.88,8.3 | v39.62,9.1 39.62,9.15 40.4,9.15 41.15,9.9 46.82,9.9 47.2,10.28 v59.35,10.28 | 68.53,8.43 v68.53,8.38
DTO2P  (via drill 0.05 pad 0.2)
  Top 0.1: v72.85,8.8 73.3,8.8 | v35.57,10.25 35.57,7.1 35.85,6.83 U1.2P | v66.82,9.48 67.15,9.15 67.15,5.05 67.35,4.85 67.67,4.85
  Top 0.3: 59.85,7.8 v59.85,8.68 v59.85,10.53
  Bottom 0.1: v72.85,8.8 72.45,8.8 72.28,8.62 59.9,8.62 v59.85,8.68 59.85,8.85 60.57,9.58 61.45,9.58 61.6,9.43 66.82,9.43 v66.82,9.48 | v35.57,10.25 37.32,10.25 37.92,9.65 38.57,9.65 38.88,9.35 40.27,9.35 41.02,10.1 46.67,10.1 47.1,10.53 v59.85,10.53
DTON  (via drill 0.05 pad 0.2)
  Top 0.1: 73.3,9.3 72.75,9.3 v72.72,9.33 | v39.38,9.8 39.38,7.13 39.22,6.98 U1.N | R3. 68.05,8.6 68.47,9.03 71.3,9.03 v71.6,9.33
  Top 0.3: 60.85,7.8 v60.85,9.08 v60.85,11.03
  Bottom 0.1: v60.85,9.08 60.9,9.03 71.3,9.03 v71.6,9.33 v72.72,9.33 | v39.38,9.8 40.12,9.8 40.82,10.5 46.42,10.5 46.95,11.03 v60.85,11.03
DTOP  (via drill 0.05 pad 0.2)
  Top 0.1: v72.72,9.8 73.3,9.8 | v35.82,10.75 35.82,7.33 36.02,7.13 U1.P | 68.05,5.98 67.7,5.98 67.35,6.33 67.35,9.2 v67.42,9.28
  Top 0.3: 61.35,7.8 v61.35,9.28 v61.35,11.28
  Bottom 0: 67.42,9.23 v67.42,9.28
  Bottom 0.1: v61.35,9.28 61.4,9.23 67.42,9.23 71.07,9.23 71.65,9.8 v72.72,9.8 | v35.82,10.75 37.57,10.75 38.17,10.15 38.88,10.15 38.97,10.05 40.07,10.05 40.72,10.7 46.3,10.7 46.88,11.28 v61.35,11.28
FE-0N  (via drill 0.05 pad 0.2)
  Top 0.075: 70.28,16.93 69.97,17.23 69.97,18.05 | 34.8,10.48 34.75,10.43 U1.0N
  Top 0.1: v70.28,13.2 70.28,16.93 | v34.8,13.2 34.8,10.48
  Bottom 0.1: v34.8,13.2 v70.28,13.2
FE-0P  (via drill 0.05 pad 0.2)
  Top 0.075: 70.03,16.83 69.82,17.02 69.82,18.05 | U1.0P 34.6,10.43 34.55,10.48
  Top 0.1: 70.03,16.83 70.03,13.88 69.7,13.55 v69.7,12.95 | v34.55,12.95 34.55,10.48
  Bottom 0.1: v69.7,12.95 69.65,13 35.02,13 34.97,12.95 v34.55,12.95
FE-1N  (via drill 0.05 pad 0.2)
  Top 0.075: 62.67,16.93 62.38,17.23 62.38,18.05 | 34.2,10.48 34.15,10.43 U1.1N
  Top 0.1: v62.82,12.7 62.67,12.85 62.67,16.93 | v34.2,12.7 34.2,10.48
  Bottom 0.1: v62.82,12.7 62.72,12.8 35.12,12.8 35.02,12.7 v34.2,12.7
FE-1P  (via drill 0.05 pad 0.2)
  Top 0.075: 62.42,16.83 62.22,17.02 62.22,18.05 | U1.1P 34,10.43 33.95,10.48
  Top 0.1: v62.42,12.53 62.42,16.83 | v33.95,12.45 33.95,10.48
  Bottom 0.1: v62.42,12.53 62.35,12.6 35.25,12.6 35.1,12.45 v33.95,12.45
FE-2N  (via drill 0.05 pad 0.2)
  Top 0.075: 55.07,16.93 54.77,17.23 54.77,18.05 | 33.3,10.48 33.25,10.43 33.25,10.1
  Top 0.1: 55.07,16.93 55.07,13.3 54.67,12.9 46.38,12.9 46.17,12.7 v46.17,12.35 | v33.3,12.2 33.3,10.48
  Bottom 0.1: v46.17,12.35 46.17,12.4 35.38,12.4 35.17,12.2 v33.3,12.2
FE-2P  (via drill 0.05 pad 0.2)
  Top 0.075: 54.82,16.83 54.62,17.02 | 54.62,17.02 54.62,17 | 54.62,17.02 54.62,18.05 | 33.05,10.48 33.1,10.43 33.1,10.1
  Top 0.1: 54.82,16.83 54.82,13.5 54.47,13.15 46,13.15 45.82,12.98 v45.82,12.15 | v33.05,11.93 33.05,10.48
  Bottom 0.1: v45.82,12.15 45.82,12.2 35.5,12.2 35.22,11.93 v33.05,11.93
FE-3N  (via drill 0.05 pad 0.2)
  Top 0.075: 47.47,16.93 47.17,17.23 47.17,18.05 | 32.7,10.48 32.65,10.43 U1.3N
  Top 0.1: 47.47,16.93 47.47,13.65 47.22,13.4 45.77,13.4 45.57,13.2 v45.57,11.95 | v32.7,11.68 32.7,10.48
  Bottom 0.1: v45.57,11.95 45.57,12 35.62,12 35.3,11.68 v32.7,11.68
FE-3P  (via drill 0.05 pad 0.2)
  Top 0.075: 47.22,16.83 47.02,17.02 47.02,18.05 | U1.3P 32.5,10.4 32.47,10.43 32.47,10.45 32.45,10.48
  Top 0.1: 47.22,16.83 47.22,13.85 47.02,13.65 45.62,13.65 45.22,13.25 v45.22,11.75 | v32.45,11.43 32.45,10.48
  Bottom 0.1: v45.22,11.75 45.22,11.8 35.75,11.8 35.38,11.43 v32.45,11.43
FE-4N  (via drill 0.05 pad 0.2)
  Top 0.075: 39.88,16.93 39.57,17.23 39.57,18.05 | 32.1,10.48 32.05,10.43 U1.4N
  Top 0.1: v39.88,11.55 39.88,16.93 | v32.1,11.18 32.1,10.48
  Bottom 0.1: v39.88,11.55 35.85,11.55 35.47,11.18 v32.1,11.18
FE-4P  (via drill 0.05 pad 0.2)
  Top 0.075: 39.62,16.83 39.42,17.02 39.42,18.05 | U1.4P 31.9,10.43 31.85,10.48
  Top 0.1: v31.85,10.93 31.85,10.48 | v39.62,11.3 39.62,16.83
  Bottom 0.1: v39.62,11.3 35.97,11.3 35.6,10.93 v31.85,10.93
FE-5N
  Top 0.075: 32.27,16.93 31.97,17.23 31.97,18.05 | 31.5,10.48 31.45,10.43 U1.5N
  Top 0.1: 32.27,16.93 32.27,13.8 32.07,13.6 31.7,13.6 31.5,13.4 31.5,10.48
FE-5P
  Top 0.075: 32.02,16.83 31.82,17.02 31.82,18.05 | 31.25,10.48 31.3,10.43 U1.5P
  Top 0.1: 32.02,16.83 32.02,15.43 | 32.02,15.43 32.02,15.4 | 32.02,15.43 32.02,14 31.85,13.83 31.42,13.83 31.25,13.65 31.25,10.48
FE-6N  (via drill 0.05 pad 0.2)
  Top 0.075: 24.67,16.93 24.37,17.23 24.37,18.05 | 30.9,10.48 30.85,10.43 U1.6N
  Top 0.1: v24.67,12.7 24.67,16.93 | v30.9,12.7 30.9,10.48
  Bottom 0.1: v30.9,12.7 v24.67,12.7
FE-6P  (via drill 0.05 pad 0.2)
  Top 0.075: 24.42,16.83 24.22,17.02 24.22,18.05 | 30.65,10.48 30.7,10.43 U1.6P
  Top 0.1: v24.42,12.45 24.42,16.83 | v30.65,12.45 30.65,10.48
  Bottom 0.1: v30.65,12.45 v24.42,12.45
FE-7N  (via drill 0.05 pad 0.2)
  Top 0.075: 17.07,16.93 16.77,17.23 16.77,18.05 | U1.7N 30.25,10.43 30.3,10.48
  Top 0.1: v17.07,12.95 17.07,16.93 | v30.3,12.95 30.3,10.48
  Bottom 0.1: v30.3,12.95 v17.07,12.95
FE-7P  (via drill 0.05 pad 0.2)
  Top 0.075: 16.82,16.83 16.62,17.02 16.62,18.05 | 30.05,10.48 30.1,10.43 U1.7P
  Top 0.1: v16.82,13.2 16.82,16.83 | v30.05,13.2 30.05,10.48
  Bottom 0.1: v30.05,13.2 v16.82,13.2
FE-8N  (via drill 0.05 pad 0.2)
  Top 0.075: 16.32,2.68 16.62,2.38 16.62,1.55
  Top 0.1: v15.05,4.43 16.2,4.43 16.32,4.3 16.32,2.68 | U1.8N v29.95,9.73
  Bottom 0.1: v15.05,4.43 15.05,6 15.42,6.38 22.27,6.38 22.8,6.9 22.8,9.45 23.25,9.9 29.22,9.9 29.4,9.73 v29.95,9.73
FE-8P  (via drill 0.05 pad 0.2)
  Top 0.075: 16.57,2.78 16.77,2.58 16.77,1.55
  Top 0.1: v14.72,4.75 16.45,4.75 16.57,4.63 16.57,2.78 | U1.8P v29.55,10.1
  Bottom 0.1: v14.72,4.75 14.72,6.58 22.07,6.58 22.6,7.1 22.6,9.6 23.1,10.1 v29.55,10.1
FE-9N  (via drill 0.05 pad 0.2)
  Top 0.075: 23.92,2.68 24.22,2.38 24.22,1.55 | 30.6,9.68 30.55,9.73 U1.9N
  Top 0.1: 30.6,9.68 v30.6,9.48 | 23.92,2.68 23.92,5.78 23.42,6.28 23.42,7.23 23.72,7.53 v23.72,9.48
  Bottom 0.1: v30.6,9.48 v23.72,9.48
FE-9P  (via drill 0.05 pad 0.2)
  Top 0.075: 24.17,2.78 24.37,2.58 24.37,1.55 | 30.35,9.68 30.4,9.73 U1.9P
  Top 0.1: v23.67,7.1 23.67,6.35 24.17,5.85 24.17,2.78 | 30.35,9.68 v30.35,9.23
  Bottom 0.1: v30.35,9.23 24,9.23 24,7.43 v23.67,7.1
FE-10N
  Top 0.075: 31.52,2.68 31.82,2.38 31.82,1.55 | 31.2,9.68 31.15,9.73 U1.10N
  Top 0.1: 31.52,2.68 31.52,6.85 31.2,7.18 31.2,9.68
FE-10P  (via drill 0.05 pad 0.2)
  Top 0.075: 31.77,2.78 31.97,2.58 31.97,1.55 | 30.95,9.68 31,9.73 U1.10P
  Top 0.1: v31.77,7.15 31.77,2.78 | 30.95,9.68 v30.95,7.15
  Bottom 0.1: v30.95,7.15 v31.77,7.15
FE-11N  (via drill 0.05 pad 0.2)
  Top 0.075: 39.12,2.68 39.42,2.38 39.42,1.55 | 31.8,9.68 31.75,9.73 U1.11N
  Top 0.1: v39.88,8.4 39.88,6.55 39.12,5.8 39.12,2.68 | v31.8,8.98 31.8,9.68
  Bottom 0.1: v39.88,8.4 38.85,8.4 38.32,8.93 31.8,8.93 v31.8,8.98
FE-11P  (via drill 0.05 pad 0.2)
  Top 0.075: 39.38,2.78 39.57,2.58 39.57,1.55 | 31.55,9.68 31.6,9.73 U1.11P
  Top 0.1: v40.12,8.15 40.12,6.35 39.38,5.6 39.38,2.78 | v31.55,8.78 31.55,9.68
  Bottom 0.1: v40.12,8.15 38.72,8.15 38.15,8.73 31.55,8.73 v31.55,8.78
FE-12N  (via drill 0.05 pad 0.2)
  Top 0.075: 46.72,2.68 47.02,2.38 47.02,1.55 | 32.4,9.68 32.35,9.73 U1.12N
  Top 0.1: v46.72,7.85 46.72,2.68 | v32.4,9.45 32.4,9.68
  Bottom 0.1: v46.72,7.85 46.72,7.8 40.75,7.8 40.62,7.93 40.62,8.58 40.35,8.85 39.05,8.85 38.5,9.4 32.45,9.4 v32.4,9.45
FE-12P  (via drill 0.05 pad 0.2)
  Top 0.075: 46.97,2.78 47.17,2.58 47.17,1.55 | U1.12P 32.2,9.75 32.15,9.7
  Top 0.1: v46.97,7.65 46.97,2.78 | v32.15,9.2 32.15,9.7
  Bottom 0.1: v46.97,7.65 46.97,7.6 40.62,7.6 40.42,7.8 40.42,8.43 40.2,8.65 38.95,8.65 38.4,9.2 v32.15,9.2
FE-13N  (via drill 0.05 pad 0.2)
  Top 0.075: 54.32,2.68 54.62,2.38 54.62,1.55 | 33,9.68 32.95,9.73 U1.13N
  Top 0.1: 54.32,2.68 54.32,5.58 53.3,6.6 v53.3,7.45 | v33,7.68 33,9.68
  Bottom 0.1: v33,7.68 33,7.63 35.07,7.63 35.3,7.4 53.3,7.4 v53.3,7.45
FE-13P  (via drill 0.05 pad 0.2)
  Top 0.075: 54.57,2.78 54.77,2.58 54.77,1.55 | 32.75,9.68 32.8,9.73 U1.13P
  Top 0.1: 54.57,2.78 54.57,5.7 | v32.75,7.43 32.75,9.68 | 54.57,5.7 54.22,6.05 | v53.6,7.25 53.6,6.68 54.57,5.7
  Bottom 0.1: v53.6,7.25 53.6,7.2 35.15,7.2 34.92,7.43 v32.75,7.43
FE-14N  (via drill 0.05 pad 0.2)
  Top 0.075: 61.92,2.68 62.22,2.38 62.22,1.55 | 33.9,9.68 33.85,9.73 U1.14N
  Top 0.1: v61.15,7.05 61.15,6.93 61.92,6.15 61.92,2.68 | 33.9,9.68 v33.9,7.18
  Bottom 0.1: v33.9,7.18 34.85,7.18 35.02,7 61.15,7 v61.15,7.05
FE-14P  (via drill 0.05 pad 0.2)
  Top 0.075: 62.17,2.78 62.38,2.58 62.38,1.55 | 33.65,9.68 33.7,9.73 U1.14P
  Top 0.1: 33.65,9.68 v33.65,6.9 | v61.77,6.85 61.77,6.7 62.17,6.3 62.17,2.78
  Bottom 0.1: v61.77,6.85 61.77,6.8 34.9,6.8 34.9,6.83 34.82,6.9 v33.65,6.9
FE-15N  (via drill 0.05 pad 0.2)
  Top 0.075: 69.53,2.68 69.82,2.38 69.82,1.55 | 34.5,9.68 34.45,9.73 U1.15N
  Top 0.1: v69.53,6.65 69.53,2.68 | 34.5,9.68 v34.5,6.65
  Bottom 0.1: v69.53,6.65 69.53,6.6 34.5,6.6 v34.5,6.65
FE-15P  (via drill 0.05 pad 0.2)
  Top 0.075: 69.78,2.78 69.97,2.58 69.97,1.55 | 34.25,9.68 34.3,9.73 U1.15P
  Top 0.1: v69.78,6.4 69.78,2.78 | 34.25,9.68 v34.25,6.4
  Bottom 0.1: v34.25,6.4 v69.78,6.4
HV_GUARD
  Top 0: C4. 18.1,5.3 20.42,5.3
  Top 0.1: R6. 20.47,5.3 | 18.07,5.3 13.95,5.3 13.95,11.03 23.3,11.03 23.3,7.63 22.6,6.93 22.6,5.33 R9. R6. | R6. 20.42,5.3
  Top 0.5: 22.57,6.83 R9. 20.42,5.3 18.07,5.3
LD  (via drill 0.05 pad 0.2)
  Top 0.075: 17.32,17.02 16.92,17.43 16.92,18.05 | 24.92,17.02 24.52,17.43 24.52,18.05 | 32.52,17.02 32.12,17.43 32.12,18.05 | 40.12,17.02 39.72,17.43 39.72,18.05 | 47.72,17.02 47.32,17.43 47.32,18.05 | 55.32,17.02 54.92,17.43 54.92,18.05 | 62.92,17.02 62.52,17.43 62.52,18.05 | 70.53,17.02 70.12,17.43 70.12,18.05 | 16.07,2.58 16.47,2.18 16.47,1.55 | 23.67,2.58 24.07,2.18 24.07,1.55 | 31.27,2.58 31.67,2.18 31.67,1.55 | 38.88,2.58 39.27,2.18 39.27,1.55 | 54.07,2.58 54.47,2.18 54.47,1.55 | 61.67,2.58 62.07,2.18 62.07,1.55 | 69.28,2.58 69.67,2.18 69.67,1.55 | 46.47,2.58 46.88,2.18 46.88,1.55
  Top 0.1: v72.9,5.08 73.3,5.08 | v17.32,13.95 17.32,17.02 | v24.92,13.95 24.92,17.02 | v40.12,13.95 40.12,17.02 | v47.72,13.95 47.72,17.02 | v55.32,13.95 55.32,17.02 | v62.92,13.95 62.92,17.02 | v70.53,13.95 70.53,17.02 | v16.07,3.93 16.07,2.58 | v23.67,5.65 23.67,2.58 | v31.27,5.65 31.27,2.58 | 54.07,2.58 54.07,5.45 v53.88,5.65 | v61.67,5.65 61.67,2.58 | v69.28,5.65 69.28,2.58 | v46.47,5.65 46.47,2.58 | v38.88,5.65 38.88,2.58 | v32.52,13.95 32.52,17.02 | 36.7,6.23 36.15,6.23 35.57,5.65 v34.07,5.65
  Bottom 0.1: v70.53,13.95 v62.92,13.95 v55.32,13.95 v47.72,13.95 v40.12,13.95 v32.52,13.95 v24.92,13.95 v17.32,13.95 14.42,13.95 13.75,13.28 13.75,4.03 14.17,3.6 15.75,3.6 v16.07,3.93 16.07,5.43 16.3,5.65 v23.67,5.65 26.67,5.65 27.12,5.2 28.75,5.2 29.2,5.65 v31.27,5.65 v34.07,5.65 34.3,5.65 34.75,5.2 38.42,5.2 v38.88,5.65 v46.47,5.65 v53.88,5.65 v61.67,5.65 v69.28,5.65 71.8,5.65 72.38,5.08 v72.9,5.08
LV1N  (via drill 0.05 pad 0.2)
  Top 0.075: 15.57,16.73 15.87,17.02 FE-7.0 | 23.17,16.73 23.47,17.02 FE-6.0 | 30.77,16.73 31.07,17.02 FE-5.0 | 38.38,16.73 38.67,17.02 FE-4.0 | 45.97,16.73 46.27,17.02 FE-3.0 | 53.57,16.73 53.88,17.02 FE-2.0 | 61.17,16.73 61.47,17.02 FE-1.0 | 68.78,16.73 69.07,17.02 FE-0.0 | 17.82,2.88 17.52,2.58 FE-8.0 | 25.42,2.88 25.12,2.58 FE-9.0 | 33.02,2.88 32.72,2.58 FE-10.0 | 40.62,2.88 40.32,2.58 FE-11.0 | 55.82,2.88 55.52,2.58 FE-13.0 | 63.42,2.88 63.12,2.58 FE-14.0 | 71.03,2.88 70.72,2.58 FE-15.0 | 48.22,2.88 47.92,2.58 FE-12.0
  Top 0.1: v15.57,15.2 15.57,16.73 | v23.17,15.2 23.17,16.73 | v30.77,15.2 30.77,16.73 | v38.38,15.2 38.38,16.73 | v45.97,15.2 45.97,16.73 | v53.57,15.2 53.57,16.73 | v61.17,15.2 61.17,16.73 | v68.78,15.2 68.78,16.73 | 17.82,2.88 17.82,3.68 v18.05,3.9 | v25.42,4.4 25.42,2.88 | v40.62,4.4 40.62,2.88 | 55.82,2.88 v55.82,4.4 | v63.42,4.4 63.42,2.88 | 71.03,2.88 v71.03,4.4 72.03,4.4 72.85,3.58 73.3,3.58 | v48.22,4.4 48.22,2.88 | v33.02,4.4 33.02,2.88 | 28.3,8.18 v28.67,8.18 28.67,9.6 28.55,9.73 v28.55,15.2 | v30.3,4.4 v30.3,8.18 | v24.37,8.35 24.37,8.08
  Bottom 0.1: v71.03,4.4 v63.42,4.4 v55.82,4.4 v48.22,4.4 v40.62,4.4 40.62,4.38 40.45,4.2 34.2,4.2 34,4.4 v33.02,4.4 v30.3,4.4 29.92,4.4 29.72,4.2 26.62,4.2 26.42,4.4 v25.42,4.4 18.55,4.4 v18.05,3.9 | v15.57,15.2 v23.17,15.2 v28.55,15.2 v30.77,15.2 v38.38,15.2 v45.97,15.2 v53.57,15.2 v61.17,15.2 v68.78,15.2 | v30.3,8.18 v28.67,8.18 28.52,8.33 24.4,8.33 v24.37,8.35
LV1P  (via drill 0.05 pad 0.2)
  Top 0.075: 15.32,16.83 15.72,17.23 FE-7.1 | 22.92,16.83 23.32,17.23 FE-6.1 | 30.52,16.83 30.92,17.23 FE-5.1 | 38.12,16.83 38.52,17.23 FE-4.1 | 45.72,16.83 46.12,17.23 FE-3.1 | 53.32,16.83 53.72,17.23 FE-2.1 | 60.92,16.83 61.32,17.23 FE-1.1 | 68.53,16.83 68.92,17.23 FE-0.1 | 18.07,2.78 17.67,2.38 FE-8.1 | 25.67,2.78 25.27,2.38 FE-9.1 | 33.27,2.78 32.88,2.38 FE-10.1 | 40.88,2.78 40.47,2.38 FE-11.1 | 56.07,2.78 55.67,2.38 FE-13.1 | 63.67,2.78 63.27,2.38 FE-14.1 | 71.28,2.78 70.88,2.38 FE-15.1 | 48.47,2.78 48.07,2.38 FE-12.1
  Top 0.1: v15.32,15.45 15.32,16.83 | v22.92,15.45 22.92,16.83 | v30.52,15.45 30.52,16.83 | v38.12,15.45 38.12,16.83 | v45.72,15.45 45.72,16.83 | v53.32,15.45 53.32,16.83 | v60.92,15.45 60.92,16.83 | v68.53,15.45 68.53,16.83 | 18.07,2.78 18.07,3.55 v18.42,3.9 | 25.67,2.78 v25.67,4.15 25.9,4.38 25.9,5.53 26.12,5.75 v26.12,8.03 | v33.27,4.15 33.27,2.78 | v40.88,4.15 40.88,2.78 | v56.07,4.15 56.07,2.78 | v63.67,4.15 63.67,2.78 | 71.28,2.78 v71.28,4.15 71.95,4.15 72.82,3.28 73.3,3.28 | v48.47,4.15 48.47,2.78 | v27.95,8.03 28.3,8.03 | v26.12,8.03 v26.12,15.45 | R11. 25.52,8.03 v26.12,8.03
  Bottom 0.1: v15.32,15.45 v22.92,15.45 v26.12,15.45 v30.52,15.45 v38.12,15.45 v45.72,15.45 v53.32,15.45 v60.92,15.45 v68.53,15.45 | v18.42,3.9 18.67,4.15 v25.67,4.15 26.35,4.15 26.5,4 29.92,4 30.05,4.13 33.27,4.13 v33.27,4.15 33.95,4.15 34.1,4 40.75,4 40.88,4.13 v40.88,4.15 v48.47,4.15 v56.07,4.15 v63.67,4.15 v71.28,4.15 | v26.12,8.03 v27.95,8.03
N$1  (1 unrouted)
  Top 0.1: 77.95,13.3 77.92,13.33 77.92,18.12 79.03,19.23 85.6,19.23
  Top 0.15: 79.3,17.3 80.8,17.3 | 79.3,17.3 79.3,18.8 | 77.8,17.3 79.3,17.3 | 79.3,17.3 79.3,15.8
N$2
  Top 0.1: 77.95,8.8 80.12,8.8 84.7,13.38 85.6,13.38
N$3
  Top 0.15: 8.8,2.3 7.3,2.3 | 7.3,2.3 7.3,3.8 7.3,2.3 | 7.3,2.3 5.8,2.3 | 7.3,2.3 7.3,0.8
N$4
  Top 0.1: 85.6,9.48 84.7,9.48 80.9,5.68 77.95,5.68
N$5
  Top 0.1: 85.6,8.83 84.7,8.83 81.25,5.38 77.95,5.38
N$6
  Top 0.1: 85.6,8.18 84.7,8.18 81.6,5.08 77.95,5.08
N$7
  Top 0.4: 77.95,11.3 79,11.3
  Top 0.5: 85.6,16.62 84.32,16.62 83.78,16.08
  Top 1: 79,11.3 83.78,16.08
N$8
  Top 0.1: 85.6,7.53 84.7,7.53 81.95,4.78 77.95,4.78
N$9
  Top 0.1: 85.6,6.88 84.7,6.88 82.3,4.48 77.95,4.48
N$10
  Top 0.1: JPA_.2 80.28,8.3 84.7,12.73 85.6,12.73
N$11
  Top 0.1: 85.6,6.23 84.7,6.23 82.65,4.18 77.95,4.18
N$12
  Top 0.1: 85.6,5.58 84.7,5.58 83,3.88 77.95,3.88
N$13
  Top 0.1: 85.6,4.93 84.7,4.93 83.35,3.58 77.95,3.58
N$14
  Top 0.1: JPA_.6 80.57,7.3 84.7,11.43 85.6,11.43
N$15
  Top 0.1: JPA_.4 80.42,7.8 84.7,12.08 85.6,12.08
N$16
  Top 0.1: 77.95,9.8 79.82,9.8 84.7,14.68 85.6,14.68
N$17
  Top 0.1: 77.95,9.3 79.97,9.3 84.7,14.03 85.6,14.03
N$18
  Top 0.1: JPA_.8 80.72,6.8 84.7,10.78 85.6,10.78
N$19
  Top 0.1: JPA_.0 80.88,6.3 84.7,10.12 85.6,10.12
N$20
  Top 0.1: 77.95,10.3 79.67,10.3 84.7,15.33 85.6,15.33
N$22  (via drill 0.05 pad 0.2)
  Top 0.1: v83.92,18.58 85.6,18.58 | 77.95,12.8 78.15,12.8 v78.55,13.2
